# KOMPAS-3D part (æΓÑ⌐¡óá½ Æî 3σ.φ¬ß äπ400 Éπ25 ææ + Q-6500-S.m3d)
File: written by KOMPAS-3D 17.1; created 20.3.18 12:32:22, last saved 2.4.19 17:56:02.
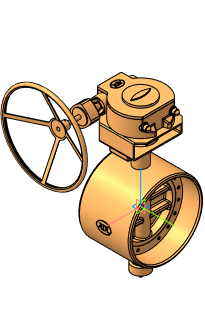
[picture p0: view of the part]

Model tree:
1. Операция без истории:2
